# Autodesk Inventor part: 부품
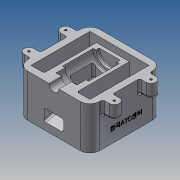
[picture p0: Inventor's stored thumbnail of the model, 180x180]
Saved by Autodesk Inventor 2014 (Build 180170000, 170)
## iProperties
Created: 2018-01
Part Number: 부품
Material: 알루미늄 6061
Document SubType Name: Modeling
Designer: 601-26
Density: 2.71 g/cm^3
Appearance: 알루미늄 - 평지
Mass: 995.109 g
Surface Area: 841.313 cm^2
Volume: 367.199 cm^3
Author: 601-26
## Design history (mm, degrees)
sketch "스케치1"
  geometry: L1 (55, -55)-(-55, -55); L2 (-55, -55)-(-55, 55); L3 (-55, 55)-(55, 55); L4 (55, 55)-(55, -55); L5 (55, -55)-(-55, 55); L6 (-55, -55)-(55, 55); 1 further point
  constraints: 12 end point, 2 midpoint, 2 parallel, 1 horizontal, 1 perpendicular
  dimensions: "d0" = 110 distance of L1.start L1.end; "d1" = 110 distance of L3.end L1.start
extrude "돌출1" new body sketch "스케치1" distance "d2" = 65; taper "d3" = 0 deg
sketch "스케치2"
  geometry: L1 (-55, -55)-(55, -55) reference; L2 (55, -55)-(55, 55) reference; L3 (55, 55)-(-55, 55) reference; L4 (-55, 55)-(-55, -55) reference; L5 (-45, 55)-(-45, 45); L6 (-55, 45)-(-45, 45); L7 (-55, 0)-(55, 0); L8 (-55, 25)-(-45, 25); L9 (-55, -25)-(-45, -25); L10 (45, 45)-(55, 45); L11 (-55, -45)-(-45, -45); L12 (45, -45)-(55, -45); L13 (45, 25)-(55, 25); L14 (45, -25)-(55, -25); L15 (-45, 25)-(35, 25); L16 (-45, 45)-(45, 45); L17 (-45, -25)-(35, -25); L18 (-45, -45)-(45, -45); L19 (55, 45)-(55, -45); L20 (-45, 45)-(-45, 25); L21 (-45, -45)-(-45, -55); L22 (-45, -25)-(-45, -45); L23 (-45, 25)-(-45, -25); L24 (35, 55)-(35, 45); L25 (35, 45)-(35, 25); L26 (35, -45)-(35, -55); L27 (35, 25)-(45, 25); L28 (35, -25)-(45, -25); L29 (35, 25)-(35, -25); L30 (35, -25)-(35, -45); L31 (45, 45)-(45, -45); 1 further point
  constraints: 54 end point, 16 perpendicular, 14 point on line, 9 parallel, 2 midpoint, 1 collinear, 1 other
  dimensions: "d4" = 10 distance between parallel lines of L4 L5; "d5" = 10 distance between parallel lines of L6 L3; "d6" = 50 distance between parallel lines of L9 L8; "d8" = 10 distance between parallel lines of L1 L11; "d9" = 20 distance between parallel lines of L19 L24; "d10" = 10 distance between parallel lines of L2 L31
extrude "돌출2" cut sketch "스케치2" distance "d11" = 110; taper "d12" = 0 deg
sketch "스케치4"
  geometry: L1 (-45, -25)-(35, -25) reference; L2 (35, -25)-(35, 25) reference; L3 (-55, 55)-(-55, -55) reference; L4 (35, 0)-(-55, 0); L5 (30, 0)-(30, -16); L6 (25, 0)-(25, -20); L7 (35, -20)-(25, -20); L8 (-22, 0)-(-22, -16); L9 (35, -16)-(30, -16); L10 (-36, -20)-(-36, -16); L11 (-55, -7.5)-(-36, -7.5); L12 (-36, -16)-(-55, -16); L13 (-36, -16)-(-36, 0); L14 (-22, -16)-(-22, -20); L15 (-22, -20)-(-55, -20); L16 (25, -16)-(-22, -16); L17 (-22, -16)-(-36, -16); L18 (25, -20)-(-22, -20); L19 (30, -16)-(30, -20); L20 (30, -16)-(25, -16); 1 further point
  constraints: 34 end point, 14 perpendicular, 14 point on line, 4 parallel, 3 midpoint
  dimensions: "d13" = 5 distance between parallel lines of L2 L5; "d14" = 5 distance between parallel lines of L6 L5; "d15" = 40 diameter of L7 L4; "d16" = 47 distance between parallel lines of L6 L8; "d17" = 32 diameter of L9 L4; "d18" = 14 distance between parallel lines of L8 L10; "d19" = 15 diameter of L11 L4
revolve "회전1" sketch "스케치4" stored, may be unused: angle "d20" = 90 deg
sketch "스케치8"
  geometry: L1 (80, -65)-(0, -65) reference; L2 (0, 0)-(80, 0) reference; L3 (0, 0)-(0, -65) reference; L4 (-10, -65)-(-10, 0) reference; L5 (-10, -35)-(90.247, -35); L6 (80, 0)-(80, -65); L7 (-10, -65)-(100, -65) reference; L8 (100, -65)-(100, 0) reference; L9 (80, 0)-(80, -65) reference; L10 (80, -35)-(0, -56.436); 1 further point
  constraints: 6 end point, 6 point on line, 2 perpendicular
  dimensions: "d44" = 30 distance between parallel lines of L1 L5; "d45" = 20 distance between parallel lines of L8 L6; "d46" = 105 deg angle of L3 L10
extrude "돌출4" cut sketch "스케치8" stored distance "d47" = 30; taper "d48" = 0 deg
sketch "스케치10"
  geometry: L1 (-25, 65)-(22, 65) reference; L2 (-25, 65)-(-25, 65) reference; L3 (22, 65)-(-25, 65) reference; L4 (22, 65)-(22, 65) reference; L5 (-35, 30)-(45, 8.564) reference; L6 (45, 65)-(45, 8.564) reference; L7 (-35, 65)-(45, 65) reference; L8 (-35, 65)-(-35, 30) reference; L9 (55, 11.061)-(-20, 31.157); L10 (55, 0)-(55, 65) reference; L11 (55, 29.061)-(17, 39.243); L12 (22, 45)-(-25, 45) reference; L13 (17, 54.243)-(-20, 54.243); L14 (17, 54.243)-(17, 39.243); L15 (-20, 54.243)-(-20, 31.157); 3 further points
  constraints: 10 end point, 2 midpoint, 2 parallel, 2 point on line, 1 perpendicular, 1 vertical alignment
  dimensions: "d55" = 5 distance between parallel lines of L5 L9; "d56" = 18 distance of L9.start L11.start; "d57" = 75 deg angle of L10 L11; "d58" = 105 deg angle of L10 L9 (derived); "d59" = 37 distance of L13.start L13.end; "d60" = 15 distance of L13.start L11.end
extrude "돌출5" cut sketch "스케치10" stored distance "d61" = 30; taper "d62" = 0 deg
sketch "스케치11"
  geometry: L1 (55, 55)-(-55, 55) reference; L2 (-55, 55)-(-55, 7.5) reference; L3 (35, 25)-(-45, 25) reference; L4 (55, 65)-(-55, 65); L5 (-28, 55)-(-28, 75); L6 (-20.5, 65)-(-20.5, 55); L7 (-35.5, 65)-(-35.5, 55); L8 (-55, 55)-(55, 55) reference; L9 (-35.5, 55)-(-20.5, 55); A1 r 7.5 centre (-28, 65) between (-20.5, 65) and (-35.5, 65); 1 further point
  constraints: 10 end point, 6 point on line, 3 perpendicular, 2 point on circle, 2 tangent, 1 centre point, 1 collinear, 1 midpoint, 1 parallel
  dimensions: "d66" = 10 distance between parallel lines of L1 L4; "d67" = 27 distance between parallel lines of L2 L5; "d68" = 15 diameter of A1
extrude "돌출6" join sketch "스케치11" distance "d69" = 20; taper "d70" = 0 deg
sketch "스케치12"
  geometry: A1 r 7.5 centre (-28, 65) between (-20.5, 65) and (-35.5, 65) reference; 2 further points
  constraints: 1 coincident
hole "구멍1" sketch "스케치12" at (-28, 65) diameter "d71" = 3.242; stored, may be unused: countersink angle "d75" = 82 deg, drill point angle "d77" = 118 deg; dims "d72" = 9, "d73" = 3.023, "d74" = 2, "d76" = 11
fillet "모깎기1" dims "d78" = 15
sketch "스케치13"
  geometry: L1 (-34.5, 0)-(-34.5, -65) reference; 2 further points
  constraints: 1 other
  dimensions: "d79" = 20 distance of point (20.5, -65) point (20.5, -45); "d80" = 55 distance from line of L1 point (20.5, -45)
extrude "돌출7" join sketch "스케치13" distance "d81" = 0.5; taper "d82" = 0 deg
fillet "모깎기2" dims "d83" = 1
fillet "모깎기3" dims "d84" = 3
fillet "모깎기4" dims "d85" = 3
fillet "모깎기5" dims "d86" = 3
fillet "모깎기6" dims "d87" = 3
fillet "모깎기7" dims "d88" = 3
node "솔리드1"
mirror "대칭1"
mirror "대칭2"
mirror "대칭3"
mirror "대칭4"
node "투영된 루프11"
node "투영된 루프12"
